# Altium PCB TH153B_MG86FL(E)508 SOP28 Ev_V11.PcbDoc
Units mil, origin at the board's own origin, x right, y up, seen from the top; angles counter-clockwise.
Board outline 2850 x 2110 mil, 2 copper layers (Top Layer, Bottom Layer); 47 components, 47 nets, 246 pads, 105 vias.
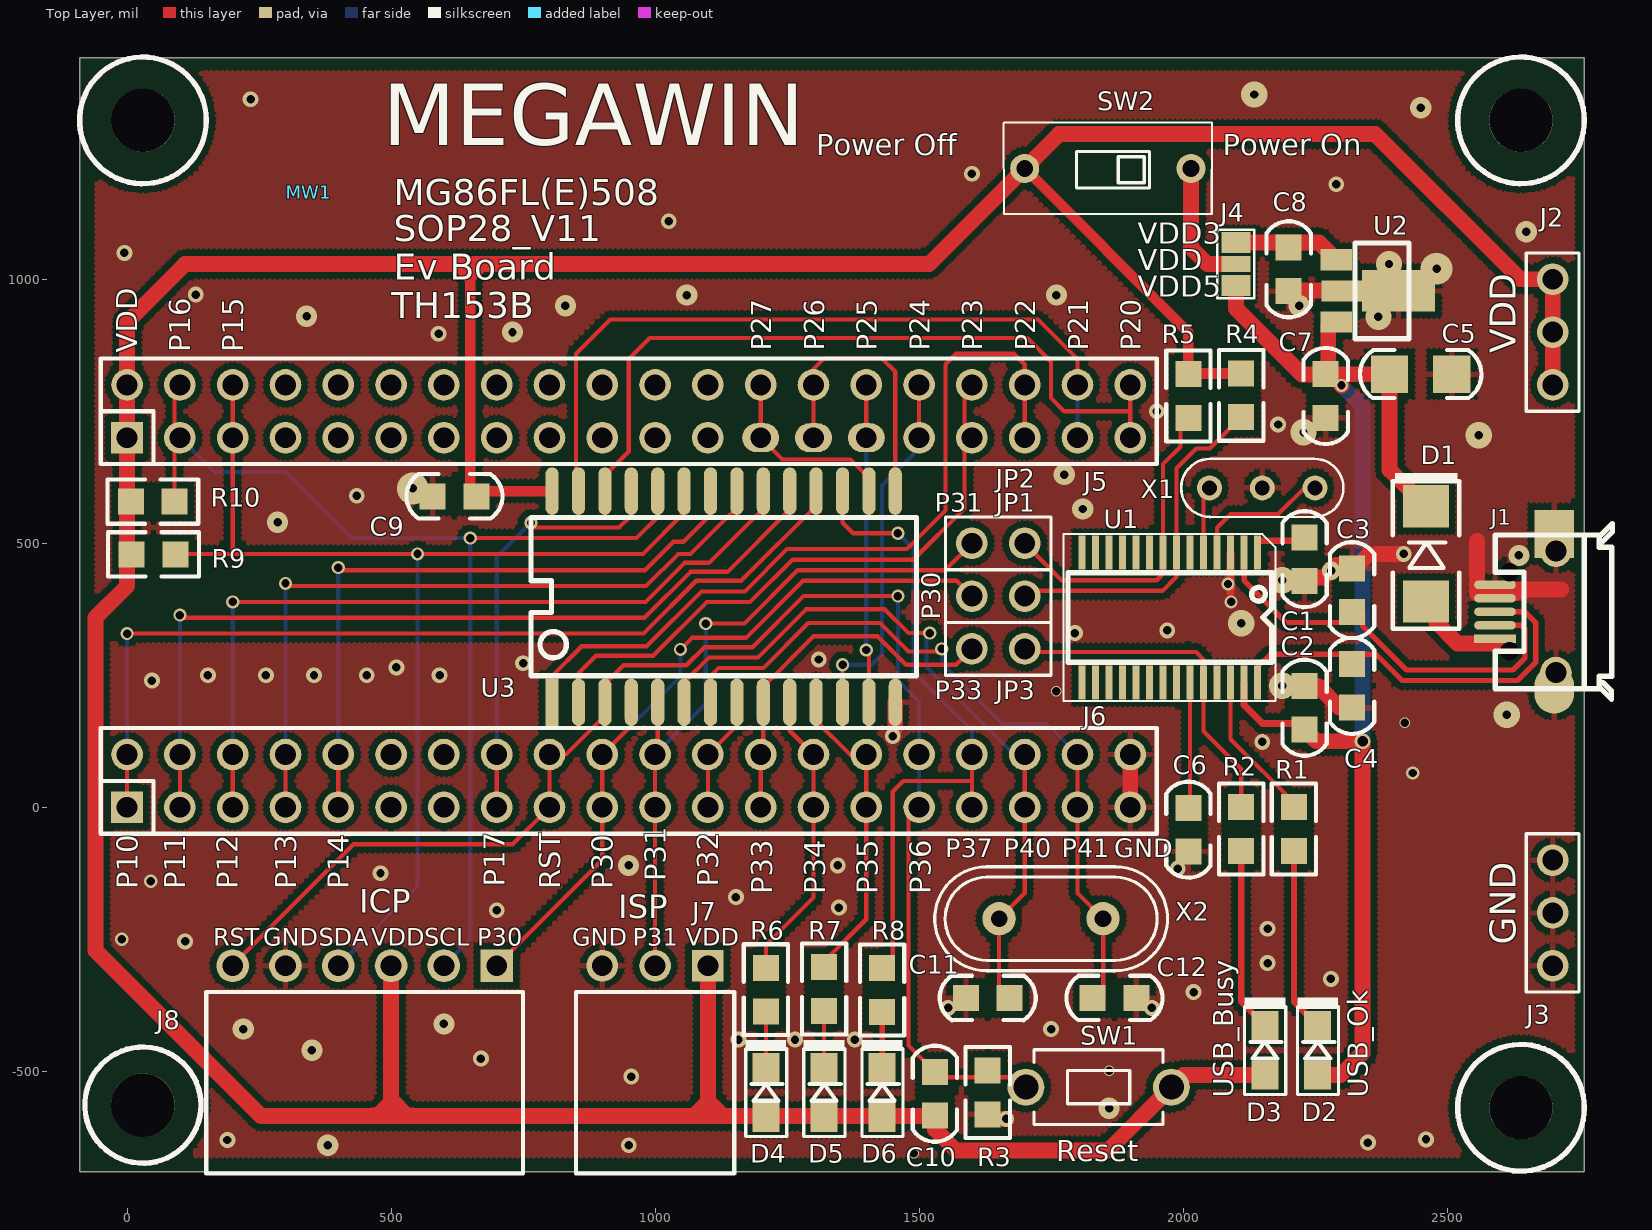
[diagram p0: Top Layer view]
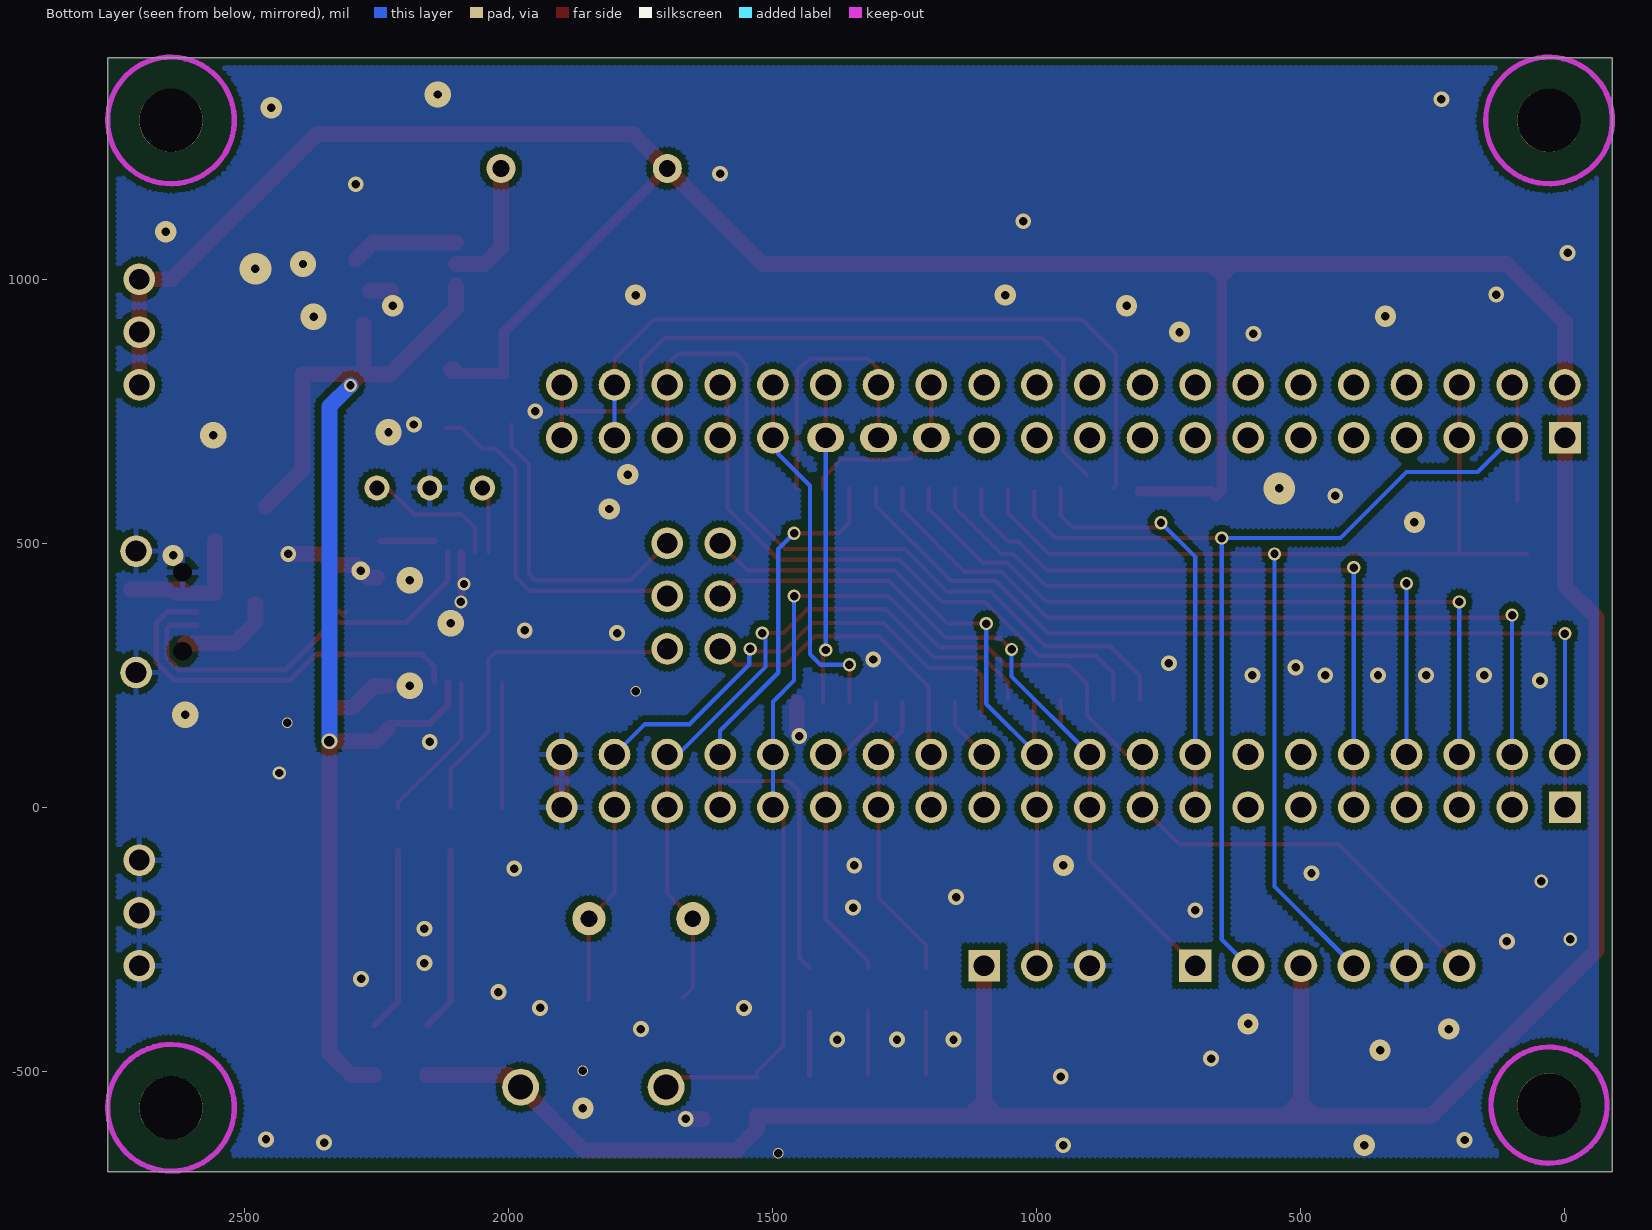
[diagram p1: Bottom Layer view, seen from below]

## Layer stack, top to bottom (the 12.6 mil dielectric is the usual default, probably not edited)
Top Layer: signal copper 1.4
Dielectric: dielectric 12.6, FR-4, Dk 4.8
Bottom Layer: signal copper 1.4

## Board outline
-90,-690 -90,1420 2760,1420 2760,-690

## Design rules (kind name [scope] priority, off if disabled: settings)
Clearance 12 [All] p1 off: gap=12
Clearance 10 [All] p2 off: gap=10
Clearance 6 [All] p3: gap=6
ComponentClearance [All] p1 off: gap=10 collisioncheckmode=3 verticalgap=10 showdistances=FALSE
HoleSize [All] p1: absolutevalues=TRUE maxlimit=500 minlimit=1 maxpercent=80.000 minpercent=20.000
MinimumSolderMaskSliver [All] p1 off: minsoldermaskwidth=10
PolygonConnect VIA [ISVIA] p1: connectstyle=Direct reliefconductorwidth=10 reliefentries=4 polygonreliefangle="90 Angle"
PolygonConnect [All] p2: connectstyle=Relief reliefconductorwidth=10 reliefentries=4 polygonreliefangle="90 Angle"
RoomDefinition "TH153B_MG86FL(E)508 SOP28 Ev_V10" [InComponentClass('TH153B_MG86FL(E)508 SOP28 Ev_V10')] p1: confinementstyle=ConfineIn formatcopy=TRUE lockcomponents=FALSE outline -545,-1285 3055,-1285 3055,1775 -545,1775
RoutingVias [All] p1: holewidth=16 width=25 viastyle="Through Hole" minholewidth=16 minwidth=24 maxholewidth=28 maxwidth=50
SilkToSilkClearance [All] p1 off: silktosilkclearance=10
SilkscreenOverComponentPads [All] p1 off: minsilkscreentomaskgap=10
SolderMaskExpansion [All] p1 off: expansion=4
Width [All] p1: maxlimit=200 minlimit=6 preferedwidth=10
23 further rules are at their usual default settings.

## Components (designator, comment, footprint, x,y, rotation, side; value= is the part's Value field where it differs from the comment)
C1 "4.7uF" 0805C 2230,470 r270 top
C2 "0.1uF" 0805C 2230,188.66 r270 top
C3 "15pF" 0805C 2320,411.34 r90 top
C4 "15pF" 0805C 2320,230 r270 top
C5 "4.7uF" 1206C 2450,820.34 r0 top
C6 "0.1uF" 0805C 2010,-42.34 r90 top
C7 "0.1uF" 0805C 2270,779 r270 top
C8 "4.7uF" 0805C 2200,1019 r270 top
C9 "0.1uF" 0805C 620,589 r180 top
C10 "1u" 0805C 1530,-542.34 r90 top
C11 "NC" 0805C 1630,-361 r180 top
C12 "NC" 0805C 1870,-361 r0 top
D1 "1N5817" D5817_SMD_1 2460,480 r270 top
D2 "Yellow" 0805D 2255,-460 r90 top
D3 "RED" 0805D 2155,-460 r90 top
D4 "Green" 0805D 1210,-540 r90 top
D5 "RED" 0805D 1320,-540 r90 top
D6 "Green" 0805D 1430,-540 r90 top
J1 "Micro USB母座" JACK_USB_SMD290X220P065 2590.71,370.28 r180 top
J2 "*" PS3P254 2700,800 r90 top
J3 "*" PS3P254 2700,-100 r270 top
J4 "*" JUMP3_SMD 2100,1029 r90 top
J5 "*" PS20X2P254#1 0,700 r0 top locked
J6 "*" PS20X2P254#2 0,0 r0 top locked
J7 "*" PS3P254f_90 1100,-300 r180 top
J8 "*" PS6P254F_90 700,-300 r180 top
JP1 "JUMPER2" PS2P254 1600,400 r0 top
JP2 "JUMPER2" PS2P254 1600,500 r0 top
JP3 "JUMPER2" PS2P254 1600,300 r0 top
MW1 "MW-A4" MEGAWIN_T 344.19,1165.19 r0 top
R1 "1K" 0805R 2210,-41 r270 top
R2 "1K" 0805R 2110,-41 r270 top
R3 "47K" 0805R 1630,-540 r90 top
R4 "4.7K" 0805R 2110,780.34 r270 top
R5 "4.7K" 0805R 2010,779 r270 top
R6 "1K" 0805R 1210,-345.42 r270 top
R7 "1K" 0805R 1320,-344.08 r270 top
R8 "1K" 0805R 1430,-346 r270 top
R9 "4.7K" 0805R 50,479 r180 top
R10 "4.7K" 0805R 48.66,579 r180 top
SW1 "SW TACT-SPST" SW_T_2P 1840,-530 r180 top
SW2 "-" DIP2_SW 2014.96,1210 r180 top
U1 "MA101_TSSOP28" TSSOP28_170P065 1974.84,359.52 r180 top
U2 "AIC1734-33(SOT-89)" SOT89 2290,978.06 r270 top
U3 "MG86FE(L)508_SOP-28" SO28_300P127 1130,399 r0 top locked (schematic designator U1)
X1 "6MHz" X3P 2250,605 r180 top
X2 "NC" X49U 1750,-211 r0 top

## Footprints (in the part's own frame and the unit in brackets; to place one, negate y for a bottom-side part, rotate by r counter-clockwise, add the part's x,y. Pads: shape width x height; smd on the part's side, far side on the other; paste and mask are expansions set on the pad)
0805C [mm]
  rect 1.25x1.25 smd: 1(-1.05,0) 2(1.05,0)
  silkscreen extent -2.31,-1.07 2.31,1.07
0805D [mm]
  rect 1.4x1.3 smd: 1(-1.192,0) 2(1.192,0)
  silkscreen extent -2.12,-1 2.53,0.98
0805R [mm]
  rect 1.25x1.25 smd: 1(-1.05,0) 2(1.05,0)
  silkscreen extent -2.18,-1.07 2.18,1.07
1206C [mm]
  rect 1.8x1.8 smd: 1(-1.5,0) 2(1.5,0)
  silkscreen extent -2.92,-1.15 2.92,1.16
D5817_SMD_1 [mil]
  rect 80x86.61 smd: 1(90,0) 2(-90,0)
  silkscreen extent -153,-63 142,63
DIP2_SW [mm]
  round 1.4 hole 0.8: 1(0,0) 2(8,0)
  silkscreen extent -1.02,-2.2 9.02,2.2
JACK_USB_SMD290X220P065 [mm]
  rect 1.9x1.8 on Mech2: 0(-2.85,-1.15) 0(-2.85,1.15)
  round 0.8 hole 0.9 unplated: 1(-0.7,1.9) 5(-0.7,-1.9)
  rect 2x0.4 smd: 1(0,1.3)
  oval 2x0.4 smd: 2(0,0.65) 3(0,0) 4(0,-0.65) 5(0,-1.3)
  round 1.524 hole 1: 5(-2.931,2.921) 5(-2.931,-2.921)
  oval 1.9x2.3 smd: 5(-2.85,3.75)
  rect 1.9x2.3 smd: 5(-2.85,-3.75)
  silkscreen extent -5.65,-4.25 -0.01,4.2
JUMP3_SMD [mil]
  rect 40x55 smd: 1(-41,0) 3(41,0)
  rect 30x55 smd: 2(0,0)
  silkscreen extent -65,-35 65,35
MEGAWIN_T [mil]
PS2P254 [mil]
  round 60 hole 39.37: 1(0,0) 2(100,0)
  silkscreen extent -50,-50 150,50
PS3P254 [mil]
  round 60 hole 39.37: 1(0,0) 2(100,0) 3(200,0)
  silkscreen extent -50,-50 250,50
PS3P254f_90 [mil]
  rect 60x60 hole 39.37: 1(0,0)
  round 60 hole 39.37: 2(100,0) 3(200,0)
  silkscreen extent -50,50 250,394
PS6P254F_90 [mil]
  rect 62x62 hole 39.37: 1(0,0)
  round 62 hole 39.37: 2(100,0) 3(200,0) 4(300,0) 5(400,0) 6(500,0)
  silkscreen extent -50,50 550,394
PS20X2P254#1 [mil]
  rect 60x60 hole 39.37: 1(0,0)
  round 60 hole 39.37: 2(0,100) 3(100,0) 4(100,100) 5(200,0) 6(200,100) 7(300,0) 8(300,100) 9(400,0) 10(400,100) 11(500,0) 12(500,100) 13(600,0) 14(600,100) 15(700,0) 16(700,100) 17(800,0) 18(800,100) 19(900,0) 20(900,100) 21(1000,0) 22(1000,100) 23(1100,0) 24(1100,100) 26(1200,100) 28(1300,100) 30(1400,100) 31(1500,0) 32(1500,100) 33(1600,0) 34(1600,100) 35(1700,0) 36(1700,100) 37(1800,0) 38(1800,100) 39(1900,0) 40(1900,100)
  oval 70x55 hole 39.37: 25(1200,0) 27(1300,0) 29(1400,0)
  silkscreen extent -50,-50 1950,150
PS20X2P254#2 [mil]
  rect 60x60 hole 39.37: 1(0,0)
  round 60 hole 39.37: 2(0,100) 3(100,0) 4(100,100) 5(200,0) 6(200,100) 7(300,0) 8(300,100) 9(400,0) 10(400,100) 11(500,0) 12(500,100) 13(600,0) 14(600,100) 15(700,0) 16(700,100) 17(800,0) 18(800,100) 19(900,0) 20(900,100) 21(1000,0) 22(1000,100) 23(1100,0) 24(1100,100) 25(1200,0) 26(1200,100) 27(1300,0) 28(1300,100) 29(1400,0) 30(1400,100) 31(1500,0) 32(1500,100) 33(1600,0) 34(1600,100) 35(1700,0) 36(1700,100) 37(1800,0) 38(1800,100) 39(1900,0) 40(1900,100)
  silkscreen extent -50,-50 1950,150
SO28_300P127 [mil]
  rect 25x90 smd: 1(-325,-200)
  oval 25x90 smd: 2(-275,-200) 3(-225,-200) 4(-175,-200) 5(-125,-200) 6(-75,-200) 7(-25,-200) 8(25,-200) 9(75,-200) 10(125,-200) 11(175,-200) 12(225,-200) 13(275,-200) 14(325,-200) 15(325,200) 16(275,200) 17(225,200) 18(175,200) 19(125,200) 20(75,200) 21(25,200) 22(-25,200) 23(-75,200) 24(-125,200) 25(-175,200) 26(-225,200) 27(-275,200) 28(-325,200)
  silkscreen extent -365,-150 365,150
SOT89 [mm]
  rect 1.016x1.5 smd: 1(-1.5,0) 3(1.5,0)
  rect 2x3.5 smd: 2(0,3)
  rect 1.016x2.6 smd: 2(0,0.6)
  silkscreen extent -2.3,0.9 2.3,3.5
SW_T_2P [mil]
  round 70 hole 47.24: 1(-137.79,0) 2(137.79,0)
  silkscreen extent -122,-71 122,71
TSSOP28_170P065 [mil]
  rect 13x65 smd: 1(-166.34,-123) 2(-140.75,-123) 3(-115.16,-123) 4(-89.57,-123) 5(-63.98,-123) 6(-38.39,-123) 7(-12.79,-123) 8(12.8,-123) 9(38.39,-123) 10(63.98,-123) 11(89.57,-123) 12(115.16,-123) 13(140.75,-123) 14(166.34,-123) 15(166.34,123) 16(140.75,123) 17(115.16,123) 18(89.57,123) 19(63.98,123) 20(38.39,123) 21(12.8,123) 22(-12.79,123) 23(-38.39,123) 24(-63.98,123) 25(-89.57,123) 26(-115.16,123) 27(-140.75,123) 28(-166.34,123)
  silkscreen extent -200,-158 201,158
X3P [mm]
  round 1.2 hole 0.711: 1(0,0) 2(5.08,0) 3(2.54,0)
  silkscreen extent -1.36,-1.4 6.44,1.4
X49U [mm]
  round 1.6 hole 0.8: 1(-2.5,0) 2(2.5,0)
  silkscreen extent -5.6,-2.5 5.6,2.5

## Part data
C1 C5 C8: library part CAP
C2 C3 C4 C6 C7 C9: library part "CAP NP"
C10: library part C
C11 C12: library part "C NP"
D1: library part DIODE_ZD, "Schottky Diode"
D2 D3 D4 D5 D6: library part LED
J1: library part CON5, "Connector"
J2 J3 J4 J7: library part CON3
J5 J6: library part CON40A
J8: library part CON6
R1 R2 R4 R5 R6 R7 R8: library part R_Dup1
R3 R9 R10: library part R
SW2: library part SW-2
U2: library part AIC1734-33(SOT-89)_0
U3: library part MG86FE(L)508_DIP-28
X1: library part CRYSTAL_RC
X2: library part CRYSTAL

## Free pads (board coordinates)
  round 120 hole 120 unplated: 0(30,-564) 0(30,1301) 0(2640,-569) 0(2640,1301)

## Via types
v1: diameter 30, hole 16, Top Layer to Bottom Layer, tented both sides, 48 vias
v2: diameter 25, hole 16, Top Layer to Bottom Layer, tented both sides, 22 vias
v3: diameter 40, hole 16, Top Layer to Bottom Layer, tented both sides, 18 vias
v4: diameter 50, hole 16, Top Layer to Bottom Layer, tented both sides, 9 vias
v5: diameter 20, hole 16, Top Layer to Bottom Layer, tented both sides, 4 vias
v6: diameter 60, hole 16, Top Layer to Bottom Layer, tented both sides, 2 vias
v7: diameter 30, hole 20, Top Layer to Bottom Layer, tented both sides, 1 vias
v8: diameter 35, hole 16, Top Layer to Bottom Layer, tented both sides, 1 vias

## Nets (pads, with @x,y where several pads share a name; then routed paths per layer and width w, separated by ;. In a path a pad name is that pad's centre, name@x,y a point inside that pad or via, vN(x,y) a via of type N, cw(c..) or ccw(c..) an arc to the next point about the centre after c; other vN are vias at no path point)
D+: C4.1 J1.3 U1.28 | length 803.6
  Top Layer w10: C4.1@2330.28,281.61 C4.1@2321.89,290 ; J1.3 2647.64,370.28 2667.71,350.2 2667.71,274.55 2633.16,240 2415,240 2365,290 C4.1@2321.89,290 ; U1.28@2141.18,266.18 2165,290 2320,290 C4.1@2321.89,290 ; U1.28@2141.18,266.18 U1.28 U1.28@2141.18,266.18
D-: C3.1 J1.2 U1.2 | length 795.9
  Top Layer w10: U1.2 2115.59,429.41 2195,350 C3.1@2320,350 ; C3.1@2310,370 C3.1@2315,365 ; C3.1 C3.1@2325,370 ; C3.1@2340,370 2340,343.28 2423.28,260 2624.87,260 2647.71,282.84 2647.71,338.12 2641.14,344.69 J1.2
GND_POWER: C1.2 C2.1 C3.2 C4.2 C5.2 C6.1 C7.2 C8.2 C9.2 C11.2 C12.2 J1.4 J1.5 J3.1 J3.2 J3.3 J6.39 J6.40 J7.3 J8.5 R3.1 U1.3 U2.2 U3.14 X1.3 | length 842.6
  Top Layer w15: 2090,406 v2@2090,416 ; U1.3 2090,423 v2@2090,416 ; v2@2091,415 v2@2090,416
  Top Layer w30: 1455,150 U3.14 ; R3.1@1632.34,-590 v1(1665,-590) ; J6.39 J6.40 ; C8.2@2223.34,979 U2.2@2263,979 ; C2.1 2255,230 2296.34,188.66 C4.2 ; C1.2@2250,435 2266,435 2280,449 2290,459 2320,459 2331.32,459 2352.32,480 ; 2367.32,480 v1@2415,480 ; 2556.57,405.32 2590.71,405.32 2630,405.32 ; 2556.57,407.91 2556.57,421.46 2556.57,505 ; 2619.25,412.32 2716.34,412.32
  other v1: 950,-640 2350,-635 190,-630 2460,-629 955,-510 670,-476 1158,-440 1265,-440 1378,-440 1750,-420 1555,-380 1941,-380 2020,-350 2280,-325 2160,-295 110,-254 2160,-230 700,-195 1348,-190 1153,-170 480,-125 1990,-116 1346,-110 2150,124 1450,135 47,240 153,250 263,250 354,250 454,250 592,250 510,265 750,273 1310,280 1795,330 1970,335 2418,480 435,590 2180,725 1950,750 590,897 130,971 -5,1050 1026,1110 2290,1180 1600,1200 234,1341
  other v2: -10,-250 45,-140 2435,65 2091,389 2085,423
  other v3: 380,-640 1860,-570 350,-460 220,-420 600,-410 950,-110 2636,477 285,540 1810,565 1775,630 730,900 340,930 830,950 2220,950 1060,970 1760,970 2650,1090 2450,1325
  other v4: 2612.91,175 2188,230 2110,349 2188,430 2560,705 2228,710.5 2370,929 2390,1029 2135,1350
  other v5: 1490,-655 1860,-498.5 2420,160 1760,220
  other v6: 541,604 2480,1020
  other v8: 2281,448
MA101_RX: JP2.2 R5.2 U1.8 | length 609.7
  Top Layer w8: JP2.2 1770,430 1950,430 1962.05,442.05 U1.8 1962.05,620 ; 1962.05,637.05 1962.05,620 ; R5.2@1995,725 1995,682.95 1962.05,650 1962.05,620
MA101_TX: JP1.2 R4.2 U1.7 | length 672.5
  Top Layer w8: JP1.2 1710,410 1961,410 1987.64,436.64 U1.7 1987.64,642.14 2025,679.5 2050.5,679.5 2090,719 R4.2@2120,719
NetC1_1: C1.1 U1.1 | length 102.5
  Top Layer w13: U1.1@2141.18,505 C1.1@2243.66,505
NetC6_2: C6.2 U1.23 | length 237.5
  Top Layer w8: C6.2@2013.23,-1 U1.23
NetD1_1: D1.1 J1.1 | length 184.5
  Top Layer w30: D1.1@2480,385 2480,350 2520,310 2590.71,310 J1.1@2612.91,310
NetD2_2: D2.2 R1.2 | length 349.4
  Top Layer w12: R1.2 2210,-368.08 D2.2
NetD3_2: D3.2 R2.2 | length 349.4
  Top Layer w12: R2.2 2110,-368.08 D3.2
NetD4_2: D4.2 R6.2 | length 120.4
  Top Layer w8: D4.2@1210,-507.16 D4.2 R6.2
NetD5_2: D5.2 R7.2 | length 121.7
  Top Layer w8: D5.2@1320,-507.16 D5.2 R7.2
NetD6_2: D6.2 R8.2 | length 119.8
  Top Layer w10: D6.2@1430,-507.16 D6.2 R8.2
NetJ4_2: J4.2 SW2.1 | length 247.9
  Top Layer w30: SW2.1 2014.96,1060.04 2046,1029 J4.2
NetU1_4: U1.4 X1.1 | length 263.8
  Top Layer w8: U1.4 2064.41,529.41 2090,555 2180,555 2230,605 X1.1
NetU1_5: U1.5 X1.2 | length 127.1
  Top Layer w8: U1.5 2038.82,593.82 X1.2
P10: J6.1 J6.2 U3.18 | length 1767.2
  Top Layer w8: J6.1 J6.2 ; v2(0,329) 978,329 1078,429 1163,429 1305,571 U3.18 U3.18@1305,604
  Bottom Layer w8: J6.2 v2(0,329)
P11: J6.3 J6.4 U3.19 | length 1643.9
  Top Layer w8: J6.3 J6.4 ; v2@100,359 980,359 1067,446 1137,446 1255,564 U3.19 U3.19@1255,604
  Bottom Layer w8: J6.4 v2(100,364)
P12: J6.5 J6.6 U3.20 | length 1507.3
  Top Layer w8: J6.5 J6.6 ; v2(200,389) 982,389 1056,463 1102,463 U3.20@1205,566 ; U3.20@1205,564 U3.20@1205,566 ; U3.20@1205,604 U3.20 U3.20@1205,566
  Bottom Layer w8: J6.6 v2(200,389)
P13: J6.7 J6.8 U3.21 | length 1376.7
  Top Layer w8: J6.7 J6.8 ; v2@300,419 983,419 1044,480 1067,480 1155,568 U3.21 U3.21@1155,604
  Bottom Layer w8: J6.8 v2(300,424)
P14: J6.9 J6.10 U3.22 | length 1252.5
  Top Layer w8: J6.9 J6.10 ; v2@400,449 981,449 1035.06,503.06 1054.06,503.06 1105,554 U3.22 U3.22@1105,604
  Bottom Layer w8: J6.10 v2(400,454)
P15: J5.5 J5.6 J8.4 R9.1 U3.23 | length 2224.5
  Top Layer w8: R9.1@71.34,479 72.34,480 200,480 ; J5.6 J5.5 200,480 ; U3.23@1055,604 U3.23 1055,558 977,480 v2(550,480) 200,480
  Bottom Layer w8: J8.4 550,-150 v2(550,480)
P16: J5.3 J5.4 J8.2 R10.1 U3.24 | length 2091
  Top Layer w8: R10.1 J5.4@90,790 ; v2(650,510) 965,510 1005,550 U3.24
  Bottom Layer w8: J5.3 165,635 300,635 425,510 v2(650,510) 650,-250 J8.2
P17: J6.15 J6.16 U3.25 | length 816.5
  Top Layer w8: J6.15 J6.16 ; v2@765,530 932,530 955,553 U3.25 U3.25@955,604
  Bottom Layer w8: J6.16 700,474 v2(765,539)
P20: J5.39 J5.40 U3.26 | length 1419.2
  Top Layer w8: U3.26@905,629 950,674 950,849 990,889 1705,889 1750,844 1750,775 1775,750 1900,750 ; J5.39@1900,684 J5.39 1900,750 ; J5.40 1900,750
P21: J5.37 J5.38 U3.27 | length 1414.1
  Top Layer w8: U3.27@855,604 850,609 850,859 915,924 1725,924 1800,849 J5.38
  Bottom Layer w8: J5.37 J5.38
P22: J5.35 J5.36 U3.1 | length 1502.2
  Top Layer w8: U3.1@805,204 805,249 861,305 984,305 1088,409 1170,409 1250,489 1476.92,489 1550,562.08 1550,839 1570,859 1680,859 1700,839 J5.36 J5.35
P23: J5.33 J5.34 U3.2 | length 1150
  Top Layer w8: U3.2@855,204 855,254 888,287 996,287 1098,389 1180,389 1260,469 1489,469 1585.79,565.79 1585.79,785.79 J5.34
P24: J5.31 J5.32 U3.12 | length 679.1
  Top Layer w8: U3.12 v2(1355,270) ; J5.31 J5.32
  Bottom Layer w8: v2(1355,270) 1410,270 1430,290 1430,609 1490,669 J5.31@1490,690
P25: J5.29 J5.30 U3.13 | length 601
  Top Layer w8: J5.29 J5.30 ; U3.13 v2@1405,298
  Bottom Layer w8: v2(1400,298) J5.29
P26: J5.27 J5.28 U3.15 | length 524.6
  Top Layer w8: J5.27 J5.28 1300,830 1320,850 1430,850 1455,825 U3.15@1455,604
P27: J5.25 J5.26 U3.16 | length 356.5
  Top Layer w8: J5.26 J5.25 1241,659 1370,659 1405,624 U3.16@1405,604
P30_RXD: J6.19 J6.20 J8.1 JP1.1 U3.4 | length 1487.8
  Top Layer w8: J8.1 900,-100 J6.19 J6.20 955,155 U3.4 U3.4@955,204 ; v2(1048,299) 1070,321 1172,321 1280,429 1571,429 JP1.1
  Bottom Layer w8: J6.20 1048,248 v2(1048,299)
P31_TXD: J6.21 J6.22 J7.2 JP2.1 U3.5 | length 1360.8
  Top Layer w8: J7.2 J6.21 J6.22 1005,105 U3.5 U3.5@1005,204 ; v2(1096,348) 1169,348 1270,449 1549,449 JP2.1
  Bottom Layer w8: J6.22 1096,196 v2(1096,348)
P32: J6.23 J6.24 U3.8 | length 221.8
  Top Layer w8: J6.23 J6.24 1155,155 U3.8
P33: J6.25 J6.26 JP3.1 U3.9 | length 700.2
  Top Layer w8: J6.25 J6.26 1205,105 U3.9 1205,229 1300,324 1421,324 1475,270 1570,270 JP3.1
P34: J6.27 J6.28 R6.1 U3.10 | length 559
  Top Layer w8: R6.1 1210,-261 1300,-171 J6.27 J6.28 1255,145 U3.10
P35: J6.29 J6.30 R7.1 U3.11 | length 592.4
  Top Layer w8: U3.11 1305,164 1369,100 J6.30 J6.29 1400,-212 1320,-292 R7.1
P36: C10.2 J6.17 J6.18 J6.31 J6.32 J8.6 R3.2 SW1.2 U3.3 | length 2764.7
  Top Layer w8: J8.6@200,-299 429,-70 730,-70 J6.17 J6.18 831,100 905,174 U3.3 ; U3.3@905,204 905,234 940,269 1059,269 1093,303 1184,303 1281,400 v2(1460,400) ; J6.31@1480,0 1480,-451 C10.2 1530,-511 SW1.2@1702.21,-511
  Bottom Layer w8: v2(1460,400) 1460,240 1500,200 J6.32 J6.31 ; J6.32@1520,94 J6.32@1520,100
P37: J6.33 J6.34 R8.1 U3.17 | length 1256.5
  Top Layer w8: U3.17@1355,604 U3.17 1355,539 1375,519 v2(1460,519) ; R8.1 1450,-284.66 1450,30 1470,50 1600,50 ; J6.33 1600,50 ; J6.34 1600,50
  Bottom Layer w8: v2(1460,519) 1490,489 1490,255 1600,145 J6.34
P40: C11.1 J6.35 J6.36 U3.6 X2.1 | length 1381.8
  Top Layer w8: U3.6@1055,204 1055,237 1102,284 1195,284 1286,375 1435,375 1480,330 v2(1520,330) ; C11.1 1651.57,-341.24 X2.1 1700,-162.58 J6.35 J6.36
  Bottom Layer w8: v2@1514,330 1514,266 1680,100 J6.36
P41: C12.1 J6.37 J6.38 U3.7 X2.2 | length 1424.4
  Top Layer w8: U3.7@1105,174 U3.7 ; U3.7@1105,204 U3.7 ; v2@1545,295 1480,295 1426,349 1290,349 1205,264 1120,264 1105,249 U3.7 ; J6.38 J6.37 1800,-162.58 X2.2 1848.66,-211.24 C12.1@1848.66,-365
  Bottom Layer w8: v2@1545,300 1545,270 1657.47,157.53 1742.47,157.53 J6.38
  other v2: 1543,300
USB_BUSY: JP3.2 R2.1 U1.24 | length 643.9
  Top Layer w8: JP3.2@1710,294 2025,294 2038.82,280.18 U1.24 2038.82,144.18 2110,73 R2.1
USB_OK: R1.1 U1.26 | length 285.9
  Top Layer w8: U1.26 2090,129 2210,9 R1.1
VDD: C9.1 C10.1 D3.1 D4.1 D5.1 D6.1 J2.1 J2.2 J2.3 J5.1 J5.2 J7.1 J8.3 R4.1 R5.1 R9.2 R10.2 SW1.1 SW2.2 U3.28 | length 9268.7
  Top Layer w15: 464,-583.9 500,-547.9 501,-546.9 ; 504,-546.9 541,-583.9 ; 613,1034 618,1029 649.5,997.5 ; 649,997 649.5,997.5 ; 650,997 649.5,997.5 ; 686,1034 681,1029 650,998 649.5,997.5 ; 1062,-584.9 1099,-547.9 ; 1103,-547.9 1140,-584.9
  Top Layer w20: 650,1029 650,998 650,997 650,600.34 C9.1 ; C9.1@670,599 U3.28 ; SW2.2 2010,900 R5.1 ; R5.1@2011.34,821.68 R4.1
  Top Layer w30: R9.2@0,465 R9.2@0,479 ; 464,-583.9 500,-583.9 ; J8.3 500,-547.9 500,-583.9 ; 514,-584.9 253.9,-584.9 ; 541,-583.9 500,-583.9 ; J7.1@1100,-290 J7.1 1100,-584.9 ; C10.1 C10.1@1530,-584.9 ; R4.1@2104.95,829 R4.1@2110,829 ; D3.1 2000.87,-506.92 SW1.1 1857.79,-650 1570,-650 1530,-610 C10.1@1530,-584.9 ; J2.1 J2.2 J2.3 2639,1000 2364,1275 1765,1275 SW2.2 1519,1029 681,1029 650,1029 618,1029 110,1029 0,919 J5.2 J5.1 R9.2@0,479 ; R9.2@0,479 0,419 -60,359 -60,-271 253.9,-584.9 ; 253.9,-584.9 1062,-584.9 1100,-584.9 ; 1100,-584.9 1140,-584.9 C10.1@1530,-584.9
VDD3: C8.1 J4.3 U2.1 | length 203.6
  Top Layer w30: J4.3 2257.11,1070 U2.1
VDD5: C2.2 C5.1 C7.1 D1.2 D2.1 J4.1 U1.27 U2.3 | length 2444.2
  Top Layer w13: U1.27 2115.59,193.41 2150,159 C2.2@2230,159
  Top Layer w30: J4.1 2100,945 2225,820 C7.1@2255,820 ; C2.2 2252.32,125 v7(2340,125) 2340,-465 2298.08,-506.92 D2.1 ; C7.1@2269.33,819.67 2268.66,820.34 C7.1 C7.1@2280,820.34 ; C7.1@2275,826.34 U2.3@2275,915 ; v2(2300,799) 2300,800.34 C7.1@2280,820.34 ; D1.2 2390.94,639.06 C5.1 C7.1@2280,820.34
  Bottom Layer w30: v2(2300,799) 2340,759 v7(2340,125)
pads on no net: J1.0 J5.7 J5.8 J5.9 J5.10 J5.11 J5.12 J5.13 J5.14 J5.15 J5.16 J5.17 J5.18 J5.19 J5.20 J5.21 J5.22 J5.23 J5.24 J6.11 J6.12 J6.13 J6.14 U1.6 U1.9 U1.10 U1.11 U1.12 U1.13 U1.14 U1.15 U1.16 U1.17 U1.18 U1.19 U1.20 U1.21 U1.22 U1.25

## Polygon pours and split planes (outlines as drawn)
GND_POWER on Top Layer "Bottom Layer-No Net" (hatched 90Degree grid 10 track 10, remove dead copper, pour order 1000): -58,-660 2738.18,-660 2738.18,1391 -58,1391
GND_POWER on Bottom Layer "Bottom Layer-No Net" (hatched 90Degree grid 10 track 10, remove dead copper, pour order 1001): -60,-660 2740,-660 2740,1401 -60,1401

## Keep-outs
Keep-Out Layer:
  circle w10: c2640,-569 r120
  circle w10: c30,1301 r120
  circle w10: c30,-564 r110
  circle w10: c2640,1301 r120

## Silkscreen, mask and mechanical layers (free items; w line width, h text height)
Top Overlay:
  circle w10: c2640,-569 r120
  circle w10: c30,1301 r120
  circle w10: c30,-564 r110
  circle w10: c2640,1301 r120
  text "Power Off" at 1305,1235 h40
  text "Power On" at 2075,1235 h40
  text "MG86FL(E)508" at 505,1140 h50
  text "SOP28_V11" at 505,1072 h50
  text "VDD3" at 1914.25,1067 h40
  text "VDD" at 1914.25,1017 h40
  text "Ev Board" at 505,999 h50
  text "VDD5" at 1914.25,967 h40
  text "TH153B" at 500,926 h50
  text "P27" at 1220,865 h38 r90
  text "P26" at 1320,865 h38 r90
  text "P25" at 1420,865 h38 r90
  text "P24" at 1520,865 h38 r90
  text "P23" at 1620,865 h38 r90
  text "P22" at 1720,865 h38 r90
  text "P21" at 1820,865 h38 r90
  text "P20" at 1920,865 h38 r90
  text "P16" at 120,862 h40 r90
  text "P15" at 220,862 h40 r90
  text "VDD" at 19,861 h40 r90
  text "VDD" at 2630,860 h50 r90
  text "P31" at 1530,560 h35
  text "P30" at 1540,355 h35 r90
  text "P33" at 1530,205 h35
  text "P37" at 1550,-95 h35
  text "P40" at 1660,-95 h35
  text "P41" at 1770,-95 h35.43
  text "GND" at 1870,-95 h35.43
  text "P31" at 1020,-140 h40 r90
  text "P17" at 715,-150 h40 r90
  text "P32" at 1120,-150 h40 r90
  text "P10" at 20,-155 h40 r90
  text "P11" at 110,-155 h40 r90
  text "P12" at 210,-155 h40 r90
  text "P13" at 320,-155 h40 r90
  text "P14" at 420,-155 h40 r90
  text "RST" at 820,-155 h40 r90
  text "P30" at 920,-155 h40 r90
  text "P33" at 1222,-165 h40 r90
  text "P34" at 1322,-165 h40 r90
  text "P35" at 1422,-165 h40 r90
  text "P36" at 1522,-165 h40 r90
  text "ICP" at 440,-200 h45
  text "ISP" at 930,-210 h45
  text "GND" at 2630,-260 h50 r90
  text "RST" at 162.84,-262.16 h33
  text "GND" at 257.84,-262.16 h33
  text "SDA" at 362.84,-262.16 h33
  text "VDD" at 462.84,-262.16 h33
  text "SCL" at 562.84,-262.16 h33
  text "P30" at 662.84,-262.16 h33
  text "GND" at 842.84,-262.16 h33
  text "P31" at 957.84,-262.16 h33
  text "VDD" at 1057.84,-262.16 h33
  text "USB_Busy" at 2095,-550 h38 r90
  text "USB_Ok" at 2350,-550 h38 r90
  text "Reset" at 1760,-670 h40
Mechanical 1:
  the board outline again, w13

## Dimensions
-90,-690 to 2760,-690 on Top Overlay
-90,1420 to -90,-690 on Top Overlay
